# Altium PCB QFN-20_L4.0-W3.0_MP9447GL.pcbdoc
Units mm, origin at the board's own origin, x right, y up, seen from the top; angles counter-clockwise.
Board outline 16.53 x 17.53 mm, 2 copper layers (Top Layer, Bottom Layer), stack 0 mm thick; 1 components, 0 nets, 25 pads, 0 vias.
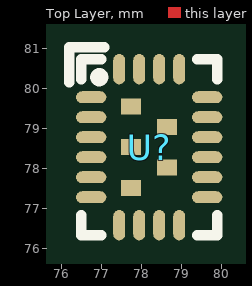
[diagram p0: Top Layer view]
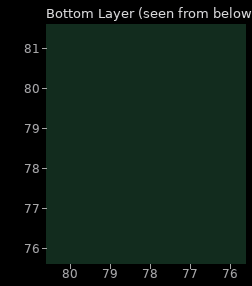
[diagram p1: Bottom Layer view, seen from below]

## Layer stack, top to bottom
Top Layer: signal copper (thickness not stored)
Bottom Layer: signal copper (thickness not stored)

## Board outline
86.38,69.85 69.85,69.85 69.85,87.38 86.38,87.38

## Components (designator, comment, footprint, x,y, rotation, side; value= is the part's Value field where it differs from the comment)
U? "" QFN-20_L4.0-W3.0_MP9447GL 78.2,78.53 r0 top

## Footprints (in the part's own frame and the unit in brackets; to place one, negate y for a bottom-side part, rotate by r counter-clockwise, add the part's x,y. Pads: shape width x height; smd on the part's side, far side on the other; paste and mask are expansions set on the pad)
QFN-20_L4.0-W3.0_MP9447GL [mm]
  oval 0.76x0.3 smd paste+0 mask+0.05: 1(-1.45,1.25) 2(-1.45,0.75) 3(-1.45,0.25) 4(-1.45,-0.25) 5(-1.45,-0.75) 6(-1.45,-1.25) 11(1.45,-1.25) 12(1.45,-0.75) 13(1.45,-0.25) 14(1.45,0.25) 15(1.45,0.75) 16(1.45,1.25)
  oval 0.3x0.76 smd paste+0 mask+0.05: 7(-0.75,-1.95) 8(-0.25,-1.95) 9(0.25,-1.95) 10(0.75,-1.95) 17(0.75,1.95) 18(0.25,1.95) 19(-0.25,1.95) 20(-0.75,1.95)
  rect 0.5x0.4 smd: 21(-0.45,1.02) 22(-0.45,0) 23(-0.45,-1.02) 24(0.45,0.51) 25(0.45,-0.51)
  silkscreen extent -2,-2.2 1.7,2.5

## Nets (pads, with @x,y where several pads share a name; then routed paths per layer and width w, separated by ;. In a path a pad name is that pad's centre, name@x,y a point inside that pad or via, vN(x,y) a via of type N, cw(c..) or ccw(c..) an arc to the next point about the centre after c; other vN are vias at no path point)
pads on no net: U?.1 U?.2 U?.3 U?.4 U?.5 U?.6 U?.7 U?.8 U?.9 U?.10 U?.11 U?.12 U?.13 U?.14 U?.15 U?.16 U?.17 U?.18 U?.19 U?.20 U?.21 U?.22 U?.23 U?.24 U?.25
